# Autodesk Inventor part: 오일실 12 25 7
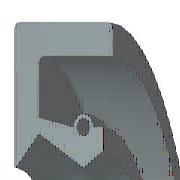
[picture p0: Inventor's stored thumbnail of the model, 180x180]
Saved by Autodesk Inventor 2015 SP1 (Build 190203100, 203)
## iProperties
IsCustomPart: 1
Created: 2012-02
Part Number: 오일실 12 25 7
Material: 고무
Description: 오일-실
Document SubType Name: Modeling
Standard: KS B 2804
Designer: test
Standards Organization: KS
Language: ko-KR
Size Designation: D - 12 25 7
Categories: <MemberInstance><Categories><Category DisplayName="샤프트 부품" InternalName="7f7aeb1f-a693-4053-b835-cee3144e0d98" Mnemonic="SHFT"><Category DisplayName="실링" Intern
Density: 0.93 g/cm^3
Appearance: 고무 - 검은색 - 버전 1.1
Author: test
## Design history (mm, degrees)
revolve "본체" stored, may be unused: angle "d17" = 90 deg
revolve "스프링1" stored, may be unused: angle "d18" = 90 deg
body "Solid1"
sketch "스케치1"
  geometry: L1 (0, 12.5)-(7, 12.5); L2 (7, 10.75)-(1.75, 10.75); L3 (1.75, 7.75)-(4.9, 6); L4 (4.9, 6)-(0, 6); L5 (0, 0)-(9.586, 0) reference; L6 (4.9, 6)-(6.3, 6.875); L7 (0, 18)-(0, -3) reference; L8 (-1.941, 0)-(11.507, 0) reference; L9 (4.2, 8.1)-(1.75, 8.59); L10 (1.75, 8.59)-(1.75, 10.75); L11 (0, 12.5)-(0, 6.088); L12 (4.9, 6)-(0, 6); L13 (1.75, 7.75)-(0.152, 6.028); L14 (7, 12.5)-(7, 10.75); L15 (5.6, 8.1)-(6.3, 8.1); L16 (6.3, 8.1)-(6.3, 6.875); C1 r 0.455 at (4.9, 8.1); A1 r 0.7 centre (4.9, 8.1) between (5.6, 8.1) and (4.2, 8.1); A2 r 0.088 centre (0.088, 6.088) between (0, 6.088) and (0.152, 6.028); 1 further point
  constraints: 28 end point, 5 horizontal alignment, 5 point on line, 4 point on circle, 4 vertical alignment, 3 centre point, 3 tangent, 2 collinear, 2 horizontal, 2 perpendicular, 1 coincident, 1 parallel
  dimensions: "d0" = 25 diameter of L1 L5 (= SD2); "d1" = 1.75 distance of L1.end L2.start (= SD); "d2" = 0.91 diameter of C1 (= SPDI); "d3" = 1.4 diameter of A1 (= SPDA); "d4" = 12 diameter of L3.end L5 (= NND); "d5" = 15.5 diameter of L3.start L5 (= TKDM); "d7" = 17.18 diameter of L9.end L5 (= TKDM + 0.24 x SWDT); "d8" = 1.75 distance between parallel lines of L11 L10 (= SD); "d9" = 4.9 distance from line of L11 C1.centre (= SPDST); "d10" = 16.2 diameter of C1.centre L5 (= HLDM); "d11" = 0.0875 radius of A2 (= 0.25 x LAB); "d12" = 6.3 distance between parallel lines of L11 L16 (= SDI); "d13" = 13.75 diameter of L6.end L5 (= ABDM); "d14" = 7 distance from line of L11 L1.end (= SWDT)
fillet "모깎기1" dims "d6" = 0.3 (= RR)
other parameters: "SD2" = 25 [user parameter; used in 1 equation term], "SWDT" = 7 [user parameter; used in 2 equation terms], "RR" = 0.3 [user parameter; used in 1 equation term], "SD" = 1.75 [user parameter; used in 2 equation terms], "NND" = 12 [user parameter; used in 1 equation term], "SPDA" = 1.4 [user parameter; used in 1 equation term], "SPDI" = 0.91 [user parameter; used in 1 equation term], "TKDM" = 15.5 [user parameter; used in 2 equation terms], "HLDM" = 16.2 [user parameter; used in 1 equation term], "ABDM" = 13.75 [user parameter; used in 1 equation term], "SDI" = 6.3 [user parameter; used in 1 equation term], "SPDST" = 4.9 [user parameter; used in 1 equation term], "LAB" = 0.35 [user parameter; used in 1 equation term], "d15" = 0, "d16" = 0, "d19" = 0
